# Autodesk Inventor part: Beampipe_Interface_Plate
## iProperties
Shininess: 64.0
Length Units: 11269
Angle Units: 11279
Time Units: 11290
Mass Units: 11283
Length Display Precision: 3
Angle Display Precision: 2
Compacted: True
Part Number: Beampipe_Interface_Plate
Document SubType Name: Modeling
Created: 2004-07
Designer: John Blackburn
Manufacturer: Standard
Standards Organization: Custom
Material: Aluminum-6061
Density: 0.0
Volumn: 0.0
Area: 0.0
PropertySet Name: Model Information
Control State: 0
Master: False
Checked Out: False
Author: John Blackburn
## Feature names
1. Extrusion1
2. Extrusion2
3. Mirror1
4. Hole2
5. Circular Pattern2
6. Hole4
